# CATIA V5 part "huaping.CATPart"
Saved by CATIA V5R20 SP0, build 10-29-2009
Part number: Part1
Material "Fire Red": density 7860 kg/m3, Young's modulus 2e+11 Pa, Poisson ratio 0.266
Bounding box of the stored display mesh (mm): x -14.995 to 14.995, y -14.995 to 25.571, z 0 to 150.465
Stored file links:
  C:\Users\12584\Desktop\huaping.CATPart
  D:\B20\win_b64\startup\materials\Catalog.CATMaterial
  D:\B20\win_b64\startup\materials\blue_env_512x512.jpg
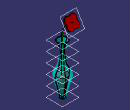
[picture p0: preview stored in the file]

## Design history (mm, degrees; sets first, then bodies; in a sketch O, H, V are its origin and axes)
Body1 (main body), material "无"
  Plane1: type Offset, RefPlane xy-plane, Offset 20
  Plane2: type Offset, RefPlane Plane1, Offset 20
  Plane3: type Offset, RefPlane Plane2, Offset 20
  Plane4: type Offset, RefPlane Plane3, Offset 20
  Plane5: type Offset, RefPlane Plane4, Offset 20
  Sketch1 on xy-plane, origin (0, 0, 0), H (1, 0, 0), V (0, 1, 0)
    circle A1 centre (0, 0) radius 5
    radius A1 = 5
  Sketch2 on Plane1, origin (0, 0, 20), H (1, 0, 0), V (0, 1, 0)
    circle A1 centre (0, 0) radius 10
    radius A1 = 10
  Sketch3 on Plane2, origin (0, 0, 40), H (1, 0, 0), V (0, 1, 0)
    circle A1 centre (0, 0) radius 15
    radius A1 = 15
  Sketch4 on Plane3, origin (0, 0, 60), H (1, 0, 0), V (0, 1, 0)
    circle A1 centre (0, 0) radius 7.5
    radius A1 = 7.5
  Sketch5 on Plane4, origin (0, 0, 80), H (1, 0, 0), V (0, 1, 0)
    circle A1 centre (0, 0) radius 5
    radius A1 = 5
  Sketch6 on Plane5, origin (0, 0, 100), H (1, 0, 0), V (0, 1, 0)
    circle A1 centre (0, 0) radius 10
  Loft1: solid, Sections (Sketch1; Sketch2; Sketch3; Sketch4; Sketch5; Sketch6)
  Shell1: IntOffset 1, Face face of Loft1, ExtOffset 0
Body2, material "Fire Red"
  Sketch7 on yz-plane, origin (0, 0, 0), H (0, 1, 0), V (0, 0, 1)
    line L1 (0, 40) -> (10, 40)
    line L2 (10, 40) -> (0, 0)
    horizontal: L1 H
  Shaft1: profile Sketch7, axis Z axis, angle 360
Body3
  Sketch8 on yz-plane, origin (0, 0, 0), H (0, 1, 0), V (0, 0, 1)
    spline S1 through (0, 0) (0, 10) (0, 20) (0, 40) (0, 50) (0, 60) (0, 80) (0, 90) (0, 110) (20, 140)
    point P1 (0, 0)
    coincidence: P1 O
  Plane6: type Normal, Curve Sketch8, RefPoint vertex of Sketch8
  Sketch9 on Plane6, origin (0, 76.7448, 46.6519), H (1, 0, 0), V (0, -0.5194, 0.8545)
    ellipse A1 centre (0, 110) semi-axes 14.1421, 8.165 rotation 45 from (-10, 110) to (0, 100)
    ellipse A2 centre (0, 110) semi-axes 14.1421, 8.165 rotation 315 from (0, 120) to (-10, 110)
    point P4 (10, 110)
    point P5 (10, 110)
    point P6 (0, 100)
    ellipse A3 centre (0, 110) semi-axes 14.1421, 8.165 rotation 45 from (10, 110) to (0, 120)
    ellipse A4 centre (0, 110) semi-axes 14.1421, 8.165 rotation 315 from (0, 100) to (10, 110)
    coincidence: A1 P4, A1 P5, A2 P6, A1 A3, A2 A4, P4 P5
  Pad1: profile Sketch9, direction (0, -0.8545, -0.5194), length 3
Body4
  Sketch10 on Plane6, origin (0, 76.7448, 46.6519), H (1, 0, 0), V (0, -0.5194, 0.8545)
    circle A1 centre (0, 110) radius 1
    radius A1 = 1
  Rib1: profile Sketch10, centre curve Sketch8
